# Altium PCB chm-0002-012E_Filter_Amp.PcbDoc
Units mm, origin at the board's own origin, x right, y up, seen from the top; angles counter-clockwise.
Board outline 116 x 29 mm, 4 copper layers (Top Layer, Mid-Layer 1, Mid-Layer 2, Bottom Layer); 56 components, 26 nets, 166 pads, 1068 vias.
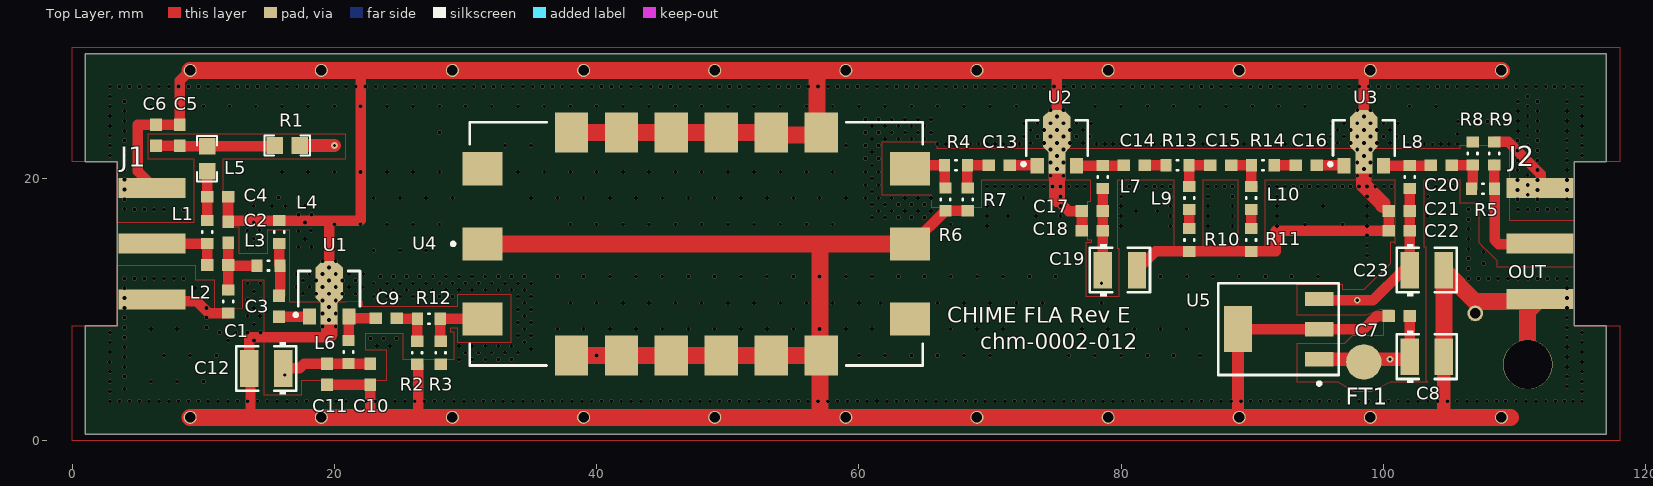
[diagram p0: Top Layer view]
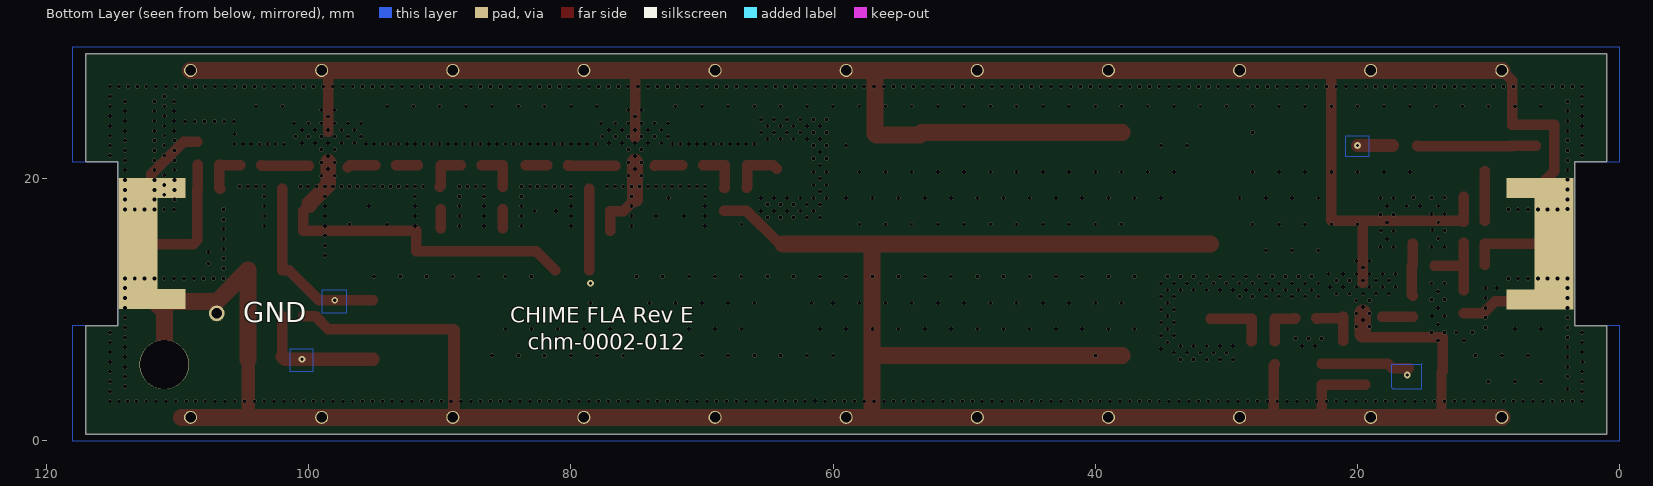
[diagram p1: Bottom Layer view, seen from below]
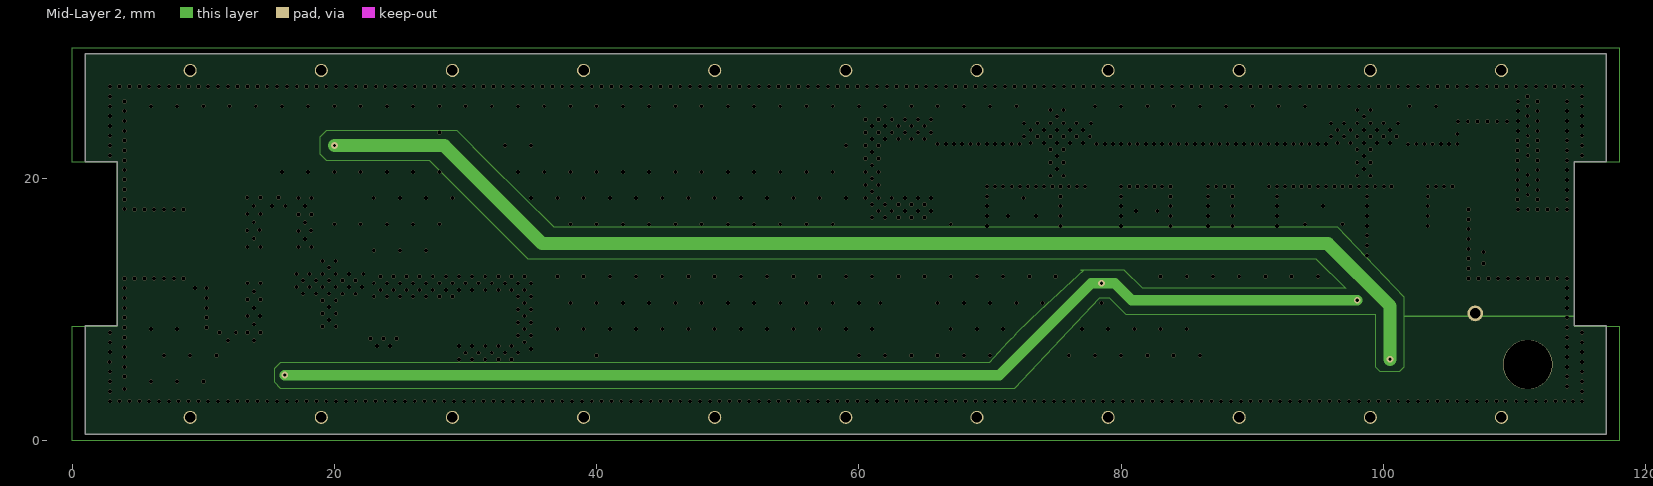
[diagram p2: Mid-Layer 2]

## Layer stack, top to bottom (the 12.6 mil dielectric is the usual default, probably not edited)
Top Solder: solder mask 0.0102, Solder Resist, Dk 3.5
Top Layer: signal copper 0.0356
Dielectric1: core 0.32, FR-4, Dk 4.8
Mid-Layer 1: signal copper 0.0356
Dielectric2: prepreg 0.32, FR-4, Dk 4.8
Mid-Layer 2: signal copper 0.0356
Dielectric3: core 0.32, FR-4, Dk 4.8
Bottom Layer: signal copper 0.0356
Bottom Solder: solder mask 0.0102, Solder Resist, Dk 3.5

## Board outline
1,0.5 1,8.75 3.45,8.75 3.45,21.25 1,21.25 1,29.5 117,29.5 117,21.25 114.55,21.25 114.55,8.75 117,8.75 117,0.5

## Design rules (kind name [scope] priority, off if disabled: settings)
AssemblyTestPointUsage [All] p0: scope1count=1 scope1_0_kind=Board scope1_0_value=Board scope2count=1 scope2_0_kind=Board scope2_0_value=Board commentlength=0
AssemblyTestpoint [All] p0: scope1count=1 scope1_0_kind=Board scope1_0_value=Board scope2count=1 scope2_0_kind=Board scope2_0_value=Board commentlength=0
Clearance [All] p0: scope1count=1 scope1_0_kind=Board scope1_0_value=Board scope2count=1 scope2_0_kind=Board scope2_0_value=Board commentlength=0 gap=0.2
Clearance [All] p1: gap=0.2
ComponentClearance [All] p0: scope1count=1 scope1_0_kind=Board scope1_0_value=Board scope2count=1 scope2_0_kind=Board scope2_0_value=Board commentlength=0 gap=0.254 collisioncheckmode=3
DiffPairsRouting [All] p0: scope1count=1 scope1_0_kind=Board scope1_0_value=Board scope2count=1 scope2_0_kind=Board scope2_0_value=Board commentlength=0
FabricationTestPointUsage [All] p0: scope1count=1 scope1_0_kind=Board scope1_0_value=Board scope2count=1 scope2_0_kind=Board scope2_0_value=Board commentlength=0 valid=0 allowmultiple=FALSE
FabricationTestpoint [All] p0: scope1count=1 scope1_0_kind=Board scope1_0_value=Board scope2count=1 scope2_0_kind=Board scope2_0_value=Board commentlength=0 side=3 testpointundercomponent=TRUE minsize=1.016 maxsize=2.54 preferedsize=1.524 minholesize=0 maxholesize=1.016 preferedholesize=0.813 testpointgrid=0.025
FanoutControl Fanout_Default [All] p0: scope1count=1 scope1_0_kind=Board scope1_0_value=Board scope2count=1 scope2_0_kind=Board scope2_0_value=Board commentlength=30 // Fanout_Default (Default Rule)
FanoutControl Fanout_Small [All] p0 off: scope1count=1 scope1_0_kind=Board scope1_0_value=Board scope2count=1 scope2_0_kind=Board scope2_0_value=Board commentlength=84 // Protel DXP Scope 1 Expression Was: (CompPinCount < 5)   Fanout_Small (Default Rule)
FanoutControl Fanout_SOIC [All] p0 off: scope1count=1 scope1_0_kind=Board scope1_0_value=Board scope2count=1 scope2_0_kind=Board scope2_0_value=Board commentlength=71 // Protel DXP Scope 1 Expression Was: IsSOIC   Fanout_SOIC (Default Rule)
FanoutControl Fanout_LCC [All] p0 off: scope1count=1 scope1_0_kind=Board scope1_0_value=Board scope2count=1 scope2_0_kind=Board scope2_0_value=Board commentlength=69 // Protel DXP Scope 1 Expression Was: IsLCC   Fanout_LCC (Default Rule)
FanoutControl Fanout_BGA [All] p0 off: scope1count=1 scope1_0_kind=Board scope1_0_value=Board scope2count=1 scope2_0_kind=Board scope2_0_value=Board commentlength=69 // Protel DXP Scope 1 Expression Was: IsBGA   Fanout_BGA (Default Rule)
Height [All] p0: scope1count=1 scope1_0_kind=Board scope1_0_value=Board scope2count=1 scope2_0_kind=Board scope2_0_value=Board commentlength=0
HoleSize [All] p0: scope1count=1 scope1_0_kind=Board scope1_0_value=Board scope2count=1 scope2_0_kind=Board scope2_0_value=Board commentlength=0 absolutevalues=TRUE maxlimit=5.5 minlimit=0.025 maxpercent=80.000 minpercent=20.000
HoleSize [All] p1: absolutevalues=TRUE maxlimit=5.5 minlimit=0.025 maxpercent=80.000 minpercent=20.000
HoleToHoleClearance [All] p0: scope1count=1 scope1_0_kind=Board scope1_0_value=Board scope2count=1 scope2_0_kind=Board scope2_0_value=Board commentlength=0
HoleToHoleClearance [All] p1: gap=0.25 allowstackedmicrovias=TRUE
LayerPairs [All] p0: scope1count=1 scope1_0_kind=Board scope1_0_value=Board scope2count=1 scope2_0_kind=Board scope2_0_value=Board commentlength=0 enforce=TRUE
MinimumSolderMaskSliver [All] p0: scope1count=1 scope1_0_kind=Board scope1_0_value=Board scope2count=1 scope2_0_kind=Board scope2_0_value=Board commentlength=0
MinimumSolderMaskSliver [All] p1: minsoldermaskwidth=0.1
NetAntennae [All] p0: scope1count=1 scope1_0_kind=Board scope1_0_value=Board scope2count=1 scope2_0_kind=Board scope2_0_value=Board commentlength=0
PasteMaskExpansion [All] p0: scope1count=1 scope1_0_kind=Board scope1_0_value=Board scope2count=1 scope2_0_kind=Board scope2_0_value=Board commentlength=0 expansion=0
PlaneClearance [All] p0: scope1count=1 scope1_0_kind=Board scope1_0_value=Board scope2count=1 scope2_0_kind=Board scope2_0_value=Board commentlength=0 clearance=0.508
PlaneConnect [All] p0: scope1count=1 scope1_0_kind=Board scope1_0_value=Board scope2count=1 scope2_0_kind=Board scope2_0_value=Board commentlength=0 planeconnectstyle=Direct reliefexpansion=0 reliefentries=4 reliefconductorwidth=0 reliefairgap=0
PlaneConnect [All] p1: planeconnectstyle=Direct reliefexpansion=0 reliefentries=4 reliefconductorwidth=0 reliefairgap=0
PolygonConnect [All] p0: scope1count=1 scope1_0_kind=Board scope1_0_value=Board scope2count=1 scope2_0_kind=Board scope2_0_value=Board commentlength=0 connectstyle=Direct reliefconductorwidth=0 reliefentries=4 polygonreliefangle="90 Angle"
PolygonConnect [All] p1: connectstyle=Direct reliefconductorwidth=0 reliefentries=4 polygonreliefangle="90 Angle" airgapwidth=0
RoutingCorners [All] p0: scope1count=1 scope1_0_kind=Board scope1_0_value=Board scope2count=1 scope2_0_kind=Board scope2_0_value=Board commentlength=0 cornerstyle=45-Degree minsetback=2.54 maxsetback=2.54
RoutingLayers [All] p0: scope1count=1 scope1_0_kind=Board scope1_0_value=Board scope2count=1 scope2_0_kind=Board scope2_0_value=Board commentlength=0 top layer=Automatic mid layer 1=Automatic mid layer 2=Automatic bottom layer=Automatic
RoutingPriority [All] p0: scope1count=1 scope1_0_kind=Board scope1_0_value=Board scope2count=1 scope2_0_kind=Board scope2_0_value=Board commentlength=0
RoutingTopology [All] p0: scope1count=1 scope1_0_kind=Board scope1_0_value=Board scope2count=1 scope2_0_kind=Board scope2_0_value=Board commentlength=0 topology=Shortest
RoutingVias [All] p0: scope1count=1 scope1_0_kind=Board scope1_0_value=Board scope2count=1 scope2_0_kind=Board scope2_0_value=Board commentlength=0 holewidth=0.711 width=1.27 viastyle="Through Hole" minholewidth=0.711 minwidth=1.27 maxholewidth=0.711 maxwidth=1.27
RoutingVias [All] p1: holewidth=0.711 width=1.27 viastyle="Through Hole" minholewidth=0.711 minwidth=1.27 maxholewidth=0.711 maxwidth=1.27
ShortCircuit [All] p0: scope1count=1 scope1_0_kind=Board scope1_0_value=Board scope2count=1 scope2_0_kind=Board scope2_0_value=Board commentlength=0 allowed=FALSE
SilkToBoardRegionClearance [All] p0: scope1count=1 scope1_0_kind=Board scope1_0_value=Board scope2count=1 scope2_0_kind=Board scope2_0_value=Board commentlength=0
SilkToSilkClearance [All] p0: scope1count=1 scope1_0_kind=Board scope1_0_value=Board scope2count=1 scope2_0_kind=Board scope2_0_value=Board commentlength=0
SilkToSilkClearance [All] p1: silktosilkclearance=0.1
SilkToSolderMaskClearance SilkscreenOverComponentPads [All] p0 off: scope1count=1 scope1_0_kind=Board scope1_0_value=Board scope2count=1 scope2_0_kind=Board scope2_0_value=Board commentlength=44 // Protel DXP Scope 1 Expression Was: IsPad
SilkToSolderMaskClearance SilkscreenOverComponentPads [IsPad] p1: minsilkscreentomaskgap=0 clearancetoexposedcopper=TRUE
SolderMaskExpansion [All] p0: scope1count=1 scope1_0_kind=Board scope1_0_value=Board scope2count=1 scope2_0_kind=Board scope2_0_value=Board commentlength=0 expansion=0.1
SolderMaskExpansion [All] p1: expansion=0.1
UnRoutedNet [All] p0: scope1count=1 scope1_0_kind=Board scope1_0_value=Board scope2count=1 scope2_0_kind=Board scope2_0_value=Board commentlength=0
UnpouredPolygon [All] p0: scope1count=1 scope1_0_kind=Board scope1_0_value=Board scope2count=1 scope2_0_kind=Board scope2_0_value=Board commentlength=0
Width [All] p0: scope1count=1 scope1_0_kind=Board scope1_0_value=Board scope2count=1 scope2_0_kind=Board scope2_0_value=Board commentlength=0 maxlimit=1.3 minlimit=0.8 preferedwidth=0.8
Width [All] p1: maxlimit=1.3 minlimit=0.8 preferedwidth=0.8
24 further rules are at their usual default settings.

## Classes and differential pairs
component class "Filter Amplifier Rev D": C1 C2 C3 C4 C5 C6 C7 C8 C9 C10 C11 C12 C13 C14 C15 C16 C17 C18 C19 C20 C21 C22 C23 L1 L2 L3 L4 L5 L6 L7 L8 L9 L10 R1 R2 R3 R4 R5 R6 R7 R8 R9 R10 R11 R12 R13 R14 U1 U2 U3 U4 U5

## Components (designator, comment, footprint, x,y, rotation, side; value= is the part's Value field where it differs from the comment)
C1 "C0603_12p" C1608-0603 11.1,13.4 r0 top
C2 "C0603_2p7" C1608-0603 11.9,15.9 r270 top
C3 "C0603_100p" C1608-0603 15.775,10.25 r270 top
C4 "C0603_100p" C1608-0603 11.1,18.6 r180 top
C5 "C0603_100p" C1608-0603 8.2,23.3 r270 top
C6 "C0603_u1" C1608-0603 6.4,23.3 r270 top
C7 "C0603_u1" C1608-0603 101.2,9.5 r0 top
C8 "Cap Tantalum CC3528" CC3528 103.3,6.4 r0 top
C9 "C0603_100p" C1608-0603 23.95,9.325 r0 top
C10 "C0603_100p" C1608-0603 22.725,5.05 r90 top
C11 "C0603_u1" C1608-0603 19.425,5.075 r90 top
C12 "Cap Tantalum CC3528" CC3528 14.8,5.5 r180 top
C13 "C0603_100p" C1608-0603 70.7,21 r0 top
C14 "C0603_100p" C1608-0603 81,21 r0 top
C15 "C0603_3p9" C1608-0603 87.6,21 r0 top
C16 "C0603_100p" C1608-0603 94.1,21 r180 top
C17 "C0603_100p" C1608-0603 77.8,17.5 r0 top
C18 "C0603_u1" C1608-0603 77.8,16 r180 top
C19 "Cap Tantalum CC3528" CC3528 103.3,13 r0 top
C20 "C0603_100p" C1608-0603 104.4,21 r0 top
C21 "C0603_100p" C1608-0603 101.2,17.5 r0 top
C22 "C0603_u1" C1608-0603 101.2,16 r0 top
C23 "Cap Tantalum CC3528" CC3528 79.9,13 r0 top
J1 "Comment" SMA_EdgeConnector 6.075,10.775 r90 top locked
J2 "Comment" SMA_EdgeConnector 111.95,19.275 r270 top
L1 "Ind0603_51nH" R0603 10.3,15.9 r270 top
L2 "Ind0603_36nH" R0603 11.9,10.6 r90 top
L3 "Ind0603_4n7H" R0603 14.975,13.35 r0 top
L4 "Ind0603_72nH" R0603 15.8,15.9 r270 top
L5 "Ind0805_100nH" "0805 LRC" 10.3,21.5 r90 top
L6 "Ind0603_100nH" R0603 21.075,6.75 r90 top
L7 "Ind0603_100nH" R0603 78.6,20.1 r90 top
L8 "Ind0603_100nH" R0603 102,20.1 r90 top
L9 "Ind0603_15nH" R0603 85.2,18.5 r90 top
L10 "Ind0603_15nH" R0603 89.9,18.5 r90 top
R1 "R0805_0R" "0805 LRC" 16.4,22.5 r0 top
R2 "R603_270R1" R0603 26.3,6.7 r90 top
R3 "R603_270R1" R0603 28.1,6.7 r90 top
R4 "R603_6R2" R0603 67.4,21 r0 top
R5 "R603_6R2" R0603 107.6,19.2 r0 top
R6 "R603_82R1" R0603 66.6,18.4 r90 top
R7 "R603_82R1" R0603 68.3,18.4 r90 top
R8 "R603_82R1" R0603 106.8,21.9 r270 top
R9 "R603_82R1" R0603 108.45,21.9 r270 top
R10 "R603_47R0" R0603 85.2,15.3 r90 top
R11 "R603_47R0" R0603 89.9,15.3 r270 top
R12 "R603_18R0" R0603 27.2,9.3 r0 top
R13 "R603_2R7" R0603 84.3,21 r0 top
R14 "R603_2R7" R0603 90.8,21 r0 top
U1 "MGA-30889" SOT-89 19.6,11.6 r90 top
U2 "MGA-30889" SOT-89 75.1,23.1 r90 top
U3 "MGA-30889" SOT-89 98.5,23.1 r90 top
U4 "BPF-600-2+" MiniCcts_HP1156 47.6,15 r90 top
U5 "LT1129IST-5" SOT-223 92,8.5 r90 top
? "" "UBC Logo" 90.975,9.575 r180 bottom
? "" "UBC Logo" 24.075,22.625 r0 top

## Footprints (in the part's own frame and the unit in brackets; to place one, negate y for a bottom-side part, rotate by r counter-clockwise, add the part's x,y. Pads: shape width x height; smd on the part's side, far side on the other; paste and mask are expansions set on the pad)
"0805 LRC" [mm] "Generic 0805 reduced footprint"
  rect 1.27x1.27 smd: 1(-0.95,0) 2(0.95,0)
  silkscreen extent -1.73,-0.76 1.73,0.76
C1608-0603 [mm] "Chip Capacitor, 2-Leads, Body 1.60x0.80mm, IPC Medium Density"
  rect 0.95x0.9 smd: 1(-0.8,0) 2(0.8,0)
CC3528 [mm]
  rect 1.4x2.8 smd: 1(-1.3,0) 2(1.3,0)
  silkscreen extent -2.3,-2 2.3,2
MiniCcts_HP1156 [mm] "Mini Circuits Filter BPF-600-2+"
  rect 2.54x3.05 smd: 1(0,16.3) 2(-5.72,16.3) 9(-5.72,-16.3) 10(0,-16.3) 11(5.72,-16.3) 18(5.72,16.3)
  rect 3.05x2.54 smd: 3(-8.51,9.525) 4(-8.51,5.715) 5(-8.51,1.905) 6(-8.51,-1.905) 7(-8.51,-5.715) 8(-8.51,-9.525) 12(8.51,-9.525) 13(8.51,-5.715) 14(8.51,-1.905) 15(8.51,1.905) 16(8.51,5.715) 17(8.51,9.525)
  silkscreen extent -9.27,-17.27 9.27,18.67
R0603 [mm] "Chip Resistor, 2-Leads, Body 1.60x0.80mm, IPC Medium Density"
  rect 0.85x0.95 smd: 1(-0.875,0) 2(0.875,0)
  silkscreen extent -0.05,-0.38 0.05,0.38
SMA_EdgeConnector [mm]
  rect 1.53x5.1 smd: 1(4.24,0) 2(0,0) 2(8.48,0)
  rect 1.53x5.1 smd far side: 2(0,0) 2(8.48,0)
  rect 9.5x3 smd far side: 2(4.24,1.05)
SOT-89 [mm] "SOT89, 3-Leads, Body 4.5x2.6mm (max), Pitch 1.50mm, Lead Span 3.6mm, IPC Medium Density"
  rect 1.2x1 smd: 1(-2.138,1.5) 3(-2.138,-1.5)
  rect 1.8x1.3 smd: 2(-1.837,0)
  oct 3.35x2.1 smd: 4(0.438,0)
  silkscreen extent -2.14,-2.35 1.34,2.67
SOT-223 [mm]
  rect 1.1x2.15 smd: 1(-2.3,-3.1) 2(0,-3.1) 3(2.3,-3.1)
  rect 3.5x2.15 smd: 4(0,3.1)
  silkscreen extent -4.27,-4.6 3.5,4.6
"UBC Logo" [mm] "UBC Silkscreen Logo - 288mil x 392mil"

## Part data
C1: "12pf 1% 0603 50V NPO"
C2: "2.7pf  +- .1pf 50V NPO(COG)"
C3 C4 C5 C9 C10 C13 C14 C16 C17 C20 C21: "100pf Ceramic NPO 0603 Capacitor"
C6 C7 C11 C18 C22: "u1 Ceramic X7R 0603 Capacitor"
C8 C12 C19 C23: "SM Tantalum Capacitor 10u 25V B-size Low ESR"
C15: "3.9pf  +-.1pf 0603 50V NPO"
L1: "51nH 2% 0603 370mA"
L2: "36nH 2% 0603"
L3: "4.7nH 2% RF Inductor"
L4: "72nH 2% 0603"
L5: "100nH 0805 Inductor"
L6 L7 L8: "100nH 0603 5% 220mA"
L9 L10: "15nH 2% 0603"
R1: "0R 0805 1% Resistor"
R2 R3: "271R 0603 0.5% Thin Film 1/16W 100ppm Resistor"
R4 R5: "6R2 0603 1/16W 1% 200ppm Thin Film Resistor"
R6 R7 R8 R9: "82R1 0.5% 25ppm 0603 Thin Film Resistor"
R10 R11: "47R 1% 200ppm 1/5W 0603 Thin Film Resistor"
R12: "18R 0603 1/16W 0.5% Thin Film Resistor"
R13 R14: "2R7 0603 1% 200ppm Thin Film Resistor"
U1 U2 U3: "40MHz-2600MHz Flat Gain High Linearity Gain Block MGA-30889"
U4: "Band Pass Filter"
U5: "LDO +5V Regulator 700mA"

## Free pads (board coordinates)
  round 1 hole 0.8: 0(9,1.77) 0(9,28.23) 0(19,1.77) 0(19,28.23) 0(29,1.77) 0(29,28.23) 0(39,1.77) 0(39,28.23) 0(49,1.77) 0(49,28.23) 0(59,1.77) 0(59,28.23) 0(69,1.77) 0(69,28.23) 0(79,1.77) 0(79,28.23) 0(89,1.77) 0(89,28.23) 0(99,1.77) 0(99,28.23) 0(109,1.77) 0(109,28.23)
  round 2.7 smd: 0(98.5,6)
  round 2.7 on Top Solder: 0(98.5,6)
  round 1.2 hole 0.8: 0(107,9.7)
  round 4 on Bottom Solder: 2(103.65,6.45)

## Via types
v1: diameter 0.3, hole 0.3, Top Layer to Bottom Layer, 1062 vias
v2: diameter 0.508, hole 0.254, Top Layer to Bottom Layer, 5 vias
v3: diameter 3.75, hole 3.73, Top Layer to Bottom Layer, 1 vias

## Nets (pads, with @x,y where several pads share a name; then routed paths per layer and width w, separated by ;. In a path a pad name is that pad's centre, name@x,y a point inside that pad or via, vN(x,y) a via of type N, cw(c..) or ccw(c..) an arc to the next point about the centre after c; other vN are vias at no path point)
GND: C2.1 C4.1 C5.1 C6.1 C7.1 C8.2 C10.1 C11.1 C12.2 C17.1 C18.2 C19.2 C21.1 C22.1 C23.2 J1.2 J2.2 L2.1 L4.1 pad.0@9,1.77 pad.0@9,28.23 pad.0@19,1.77 pad.0@19,28.23 pad.0@29,1.77 pad.0@29,28.23 pad.0@39,1.77 pad.0@39,28.23 pad.0@49,1.77 pad.0@49,28.23 pad.0@59,1.77 pad.0@59,28.23 pad.0@69,1.77 pad.0@69,28.23 pad.0@79,1.77 pad.0@79,28.23 pad.0@89,1.77 pad.0@89,28.23 pad.0@99,1.77 pad.0@99,28.23 pad.0@107,9.7 pad.0@109,1.77 pad.0@109,28.23 R2.1 R3.1 R6.1 R7.1 R8.1 R9.1 R10.1 R11.2 U1.2 U1.4 U2.2 U2.4 U3.2 U3.4 U4.1 U4.3 U4.4 U4.5 U4.6 U4.7 U4.8 U4.10 U4.12 U4.13 U4.14 U4.15 U4.16 U4.17 U5.2 U5.4 | length 459.4
  Top Layer w0.8: J1.2@6.057,10.625 9.5,10.625 10.4,9.725 L2.1 ; J1.2@6.15,19.382 5,20.532 5,24.1 C6.1 C5.1 8.2,27.43 pad.0@9,28.23 ; C2.1 C4.1 ; C2.1@11.975,16.775 L4.1 19.5,16.775 ; 13.6,1.77 13.6,5.2 13.5,5.3 13.5,7.85 13.525,7.875 19.35,7.875 19.6,8.125 ; C11.1 19.45,4.25 C10.1 22.725,1.905 22.86,1.77 ; U1.4 19.6,16.675 19.5,16.775 ; 21.9,28.23 22,28.13 22,16.8 21.975,16.775 19.5,16.775 ; R2.1 26.4,5.725 26.4,1.77 ; U4.10@63.8,15 64.075,15 R6.1 R7.1 ; 75.1,18.4 76,17.5 C17.1 C18.2 ; U2.4@75.1,23.1 75.1,28.23 ; C23.2 82.625,14.425 R11.2 91.8,14.425 91.8,16 C22.1 C21.1 C21.1@99.95,17.95 ; U5.4@88.9,8.4 89,8.5 U5.2 98.5,8.5 99.5,9.5 C7.1 ; U3.4 98.5,27.73 pad.0@99,28.23 ; 108.3,28.23 108.5,28.03 ; R9.1@108.5,22.775 109.475,22.775 109.5,22.8 112,20.3 J2.2@112,19.382
  Top Layer w0.9: U5.4@88.9,8.4 88.9,1.87 pad.0@89,1.77
  Top Layer w1: 104.5,1.77 104.6,1.87 C8.2@104.6,6.2
  Top Layer w1.2: 75.1,18.4 U2.2 ; U3.2 98.5,19.5 99.95,18.05 C21.1@99.95,17.95
  Top Layer w1.25: 19.6,8.125 U1.2
  Top Layer w1.3: pad.0@9,1.77 13.6,1.77 19,1.77 22.86,1.77 26.4,1.77 29,1.77 39,1.77 49,1.77 56.9,1.77 ; pad.0@9,28.23 19,28.23 21.9,28.23 29,28.23 39,28.23 49,28.23 56.8,28.23 ; U4.1@31.2,15 56.9,15 ; U4.3@37.975,6.49 U4.8@57.025,6.49 ; U4.17@37.975,23.51 53.215,23.51 53.425,23.3 56.7,23.3 56.8,23.4 56.8,28.23 ; 57.025,28.005 56.8,28.23 ; U4.10@63.8,15 56.9,15 ; C8.2@104.6,6.2 C19.2 106.982,10.619 111.721,10.619 111,9.898 v3(111,5.8) ; pad.0@109,28.23 108.3,28.23 99,28.23 89,28.23 79,28.23 75.1,28.23 69,28.23 59,28.23 56.8,28.23 ; 109.67,1.77 109,1.77 104.5,1.77 99,1.77 90.9,1.77 89,1.77 79,1.77 69,1.77 59,1.77 56.9,1.77 ; 56.9,1.77 57.025,1.895 U4.8@57.025,6.49 ; 56.9,15 57.025,14.875 U4.8@57.025,6.49
  other v1: 2.875,3 3.625,3 4.375,3 5.125,3 5.875,3 6.625,3 7.375,3 8.125,3 8.875,3 9.625,3 10.375,3 11.125,3 11.875,3 12.625,3 13.375,3 14.125,3 14.875,3 15.625,3 16.375,3 17.125,3 17.875,3 18.625,3 19.375,3 20.125,3 20.875,3 21.625,3 22.375,3 23.125,3 23.875,3 24.625,3 25.375,3 26.125,3 26.875,3 27.625,3 28.375,3 29.125,3 29.875,3 30.625,3 31.375,3 32.125,3 32.85,3 33.625,3 34.375,3 35.125,3 35.875,3 36.625,3 37.375,3 38.125,3 38.875,3 39.625,3 40.375,3 41.125,3 41.875,3 42.625,3 43.375,3 44.125,3 44.875,3 45.625,3 46.375,3 47.125,3 47.875,3 48.625,3 49.375,3 50.125,3 50.875,3 51.625,3 52.375,3 53.125,3 53.875,3 54.625,3 55.375,3 56.125,3 56.875,3 57.625,3 58.375,3 59.125,3 59.875,3 60.625,3 62.125,3 62.875,3 63.625,3 64.375,3 65.125,3 65.875,3 66.625,3 67.375,3 68.125,3 68.875,3 69.625,3 70.375,3 71.125,3 71.875,3 72.625,3 73.375,3 74.125,3 74.875,3 75.625,3 76.375,3 77.125,3 77.875,3 78.625,3 79.375,3 80.125,3 80.875,3 81.625,3 82.375,3 83.125,3 83.875,3 84.625,3 85.375,3 86.125,3 86.875,3 87.625,3 88.375,3 89.125,3 89.875,3 90.625,3 91.375,3 92.125,3 92.875,3 93.625,3 94.375,3 95.125,3 95.875,3 96.625,3 97.375,3 98.125,3 98.875,3 99.625,3 100.375,3 101.125,3 101.875,3 102.625,3 103.375,3 104.125,3 104.875,3 105.625,3 106.375,3 107.125,3 107.875,3 108.625,3 109.3,3 110.125,3 110.875,3 111.625,3 112.375,3 113.125,3 113.8,3 114.45,3 115.125,3 61.375,3.025 2.875,3.75 115.125,3.75 3.975,3.95 114,4.125 2.875,4.5 6,4.5 8,4.5 10,4.5 115.125,4.5 4,4.875 114,4.875 2.875,5.25 115.125,5.25 4,5.625 114,5.625 2.85,6 115.125,6 29.5,6.2 30.5,6.2 31.5,6.2 32.5,6.2 33.5,6.2 4,6.375 114,6.375 7,6.5 9,6.5 11,6.5 40,6.5 60,6.5 62,6.5 64,6.5 66,6.5 68,6.5 70,6.5 76,6.5 78,6.5 80,6.5 82,6.5 84,6.5 86,6.5 30,6.7 31,6.7 32,6.7 33,6.7 34,6.7 2.875,6.75 115.125,6.75 35,7 4,7.125 114,7.125 23.25,7.2 24.25,7.2 29.5,7.2 30.5,7.2 31.5,7.2 32.5,7.2 33.5,7.2 2.875,7.5 34.5,7.5 115.125,7.5 11.875,7.65 13.875,7.65 22.75,7.8 23.75,7.8 24.75,7.8 4,7.875 114,7.875 34,8 35,8 2.875,8.25 11.25,8.25 12.475,8.25 13.375,8.25 14.375,8.25 115.125,8.25 6,8.5 8,8.5 34.5,8.5 37,8.5 39,8.5 41,8.5 43,8.5 45,8.5 47,8.5 49,8.5 51,8.5 53,8.5 55,8.5 57,8.5 59,8.5 61,8.5 67,8.5 69,8.5 71,8.5 77,8.5 79,8.5 81,8.5 83,8.5 85,8.5 4,8.625 10.25,8.625 114,8.625 19.1,8.7 20.1,8.7 13.875,8.875 34,9 35,9 19.6,9.2 4,9.375 10.25,9.375 114,9.375 13.375,9.5 14.325,9.5 34.5,9.5 19.1,9.7 20.1,9.7 34,10 35,10 4,10.125 10.25,10.125 13.875,10.125 114,10.125 19.6,10.2 34.5,10.5 38,10.5 40,10.5 42,10.5 44,10.5 46,10.5 48,10.5 50,10.5 52,10.5 54,10.5 56,10.5 58,10.5 60,10.5 61.625,10.5 66,10.5 68,10.5 70,10.5 72,10.5 74,10.5 78.5,10.5 19.1,10.7 20.1,10.7 13.375,10.75 14.375,10.75 4,10.875 10.25,10.875 114,10.875 23,11 24,11 25,11 26,11 27,11 28,11 29,11 34,11 35,11 17.6,11.2 18.6,11.2 19.6,11.2 20.6,11.2 21.6,11.2 13.875,11.375 23.5,11.5 24.5,11.5 25.5,11.5 26.5,11.5 27.5,11.5 28.5,11.5 29.5,11.5 30.5,11.5 31.5,11.5 32.5,11.5 33.5,11.5 34.5,11.5 4,11.625 9.375,11.625 10.25,11.625 114,11.625 17.1,11.7 18.1,11.7 19.1,11.7 20.1,11.7 21.1,11.7 22.1,11.7 13.375,12 14.375,12 23,12 24,12 25,12 26,12 27,12 28,12 29,12 30,12 31,12 32,12 33,12 34,12 35,12 17.6,12.2 18.6,12.2 19.6,12.2 20.6,12.2 21.6,12.2 4,12.375 4.75,12.375 5.5,12.375 6.25,12.375 7,12.375 7.75,12.375 8.5,12.375 106.5,12.375 107.25,12.375 108,12.375 108.75,12.375 109.5,12.375 110.25,12.375 111,12.375 111.75,12.375 112.5,12.375 113.25,12.375 114,12.375 23.5,12.5 24.5,12.5 25.5,12.5 26.5,12.5 27.5,12.5 28.5,12.5 29.5,12.5 30.5,12.5 31.5,12.5 32.5,12.5 33.5,12.5 34.5,12.5 37,12.5 39,12.5 41,12.5 43,12.5 45,12.5 47,12.5 49,12.5 51,12.5 53,12.5 55,12.5 57,12.5 59,12.5 61,12.5 63,12.5 65,12.5 67,12.5 69,12.5 71,12.5 73,12.5 75,12.5 83,12.5 85,12.5 87,12.5 89,12.5 91,12.5 93,12.5 95,12.5 17.1,12.7 18.1,12.7 19.1,12.7 20.1,12.7 21.1,12.7 22.2,12.7 106.5,13.125 19.6,13.2 107.625,13.5 19.1,13.7 20.1,13.7 106.5,13.875 98.75,14.125 107.625,14.375 23,14.5 25,14.5 27,14.5 106.5,14.625 17.25,14.75 18.25,14.75 13.35,14.775 14.35,14.775 98.75,14.875 17.75,15.375 106.5,15.375 13.85,15.4 98.75,15.625 17.25,16 13.35,16.025 18.2,16.025 14.3,16.05 106.5,16.125 69.75,16.375 75.375,16.375 80,16.375 83.75,16.375 86.625,16.375 88.5,16.375 91.875,16.375 98.75,16.375 103.375,16.375 20,16.5 22,16.5 24,16.5 26,16.5 28,16.5 38,16.5 40,16.5 42,16.5 44,16.5 46,16.5 48,16.5 50,16.5 52,16.5 54,16.5 56,16.5 58,16.5 67,16.5 94,16.5 96.875,16.5 17.75,16.625 13.85,16.65 106.5,16.875 61,17 62,17 63,17 64,17 65,17 69.75,17.125 71.375,17.125 73.5,17.125 75.375,17.125 80,17.125 83.75,17.125 86.625,17.125 88.5,17.125 91.875,17.125 98.75,17.125 103.375,17.125 17.25,17.25 18.25,17.25 13.35,17.275 14.35,17.275 61.5,17.5 62.5,17.5 63.5,17.5 64.5,17.5 65.5,17.5 81.125,17.5 82.75,17.525 4.75,17.625 5.5,17.625 6.25,17.625 7,17.625 7.75,17.625 8.5,17.625 106.5,17.625 110.25,17.625 111,17.625 111.75,17.625 112.5,17.625 113.25,17.625 114,17.625 4,17.65 17.75,17.875 69.75,17.875 75.375,17.875 80,17.875 83.75,17.875 86.625,17.875 88.5,17.875 91.875,17.875 95.375,17.875 98.75,17.875 103.375,17.875 13.85,17.9 15.25,17.9 16.25,17.9 61,18 62,18 63,18 64,18 65,18 110.225,18.375 111.75,18.375 114,18.375 4,18.4 17.25,18.5 18.25,18.5 23,18.5 25,18.5 27,18.5 29,18.5 35,18.5 37,18.5 39,18.5 41,18.5 43,18.5 45,18.5 47,18.5 49,18.5 51,18.5 53,18.5 55,18.5 57,18.5 59,18.5 60.5,18.5 61.5,18.5 62.5,18.5 63.5,18.5 64.5,18.5 65.5,18.5 72.55,18.5 13.35,18.525 14.35,18.525 15.75,18.525 69.75,18.625 75.375,18.625 80,18.625 83.75,18.625 86.625,18.625 88.5,18.625 91.875,18.625 98.75,18.625 103.375,18.625 111,18.75 61,19 110.225,19.125 111.75,19.125 114,19.125 4,19.15 69.75,19.375 70.375,19.375 71,19.375 71.65,19.375 72.275,19.375 72.875,19.375 73.5,19.375 74.1,19.375 74.75,19.375 75.375,19.375 76,19.375 76.625,19.375 77.25,19.375 80,19.375 80.625,19.375 81.25,19.375 81.875,19.375 82.525,19.375 83.125,19.375 83.75,19.375 86.625,19.375 87.25,19.375 87.875,19.375 88.5,19.375 91.25,19.375 91.875,19.375 92.5,19.375 93.125,19.375 93.75,19.375 94.375,19.375 95,19.375 95.625,19.375 96.25,19.375 96.875,19.375 97.5,19.375 98.125,19.375 98.75,19.375 99.375,19.375 100.025,19.375 100.625,19.375 103.375,19.375 104,19.375 104.625,19.375 105.25,19.375 60.5,19.5 61.5,19.5 111,19.5 110.225,19.875 111.75,19.875 114,19.875 4,19.9 61,20 74.6,20.2 75.6,20.2 98,20.2 99,20.2 111,20.25 16,20.5 18,20.5 20,20.5 22,20.5 24,20.5 26,20.5 28,20.5 34,20.5 36,20.5 38,20.5 40,20.5 42,20.5 44,20.5 46,20.5 48,20.5 50,20.5 52,20.5 54,20.5 56,20.5 58,20.5 60.5,20.5 61.5,20.5 4,20.625 110.225,20.625 111.75,20.625 114,20.625 75.1,20.7 98.5,20.7 61,21 74.6,21.2 75.6,21.2 98,21.2 99,21.2 4,21.375 110.225,21.375 111.75,21.375 114,21.375 60.5,21.5 61.5,21.5 75.1,21.7 98.5,21.7 2.875,21.75 111,21.75 115.125,21.75 61,22 4,22.125 110.225,22.125 111.75,22.125 114,22.125 74.6,22.2 75.6,22.2 98,22.2 99,22.2 2.875,22.5 33,22.5 35,22.5 59,22.5 60.5,22.5 61.5,22.5 111,22.5 115.125,22.5 101.875,22.6 103.75,22.6 66,22.625 66.625,22.625 67.25,22.625 67.875,22.625 68.5,22.625 69.125,22.625 69.75,22.625 70.375,22.625 71,22.625 71.625,22.625 72.25,22.625 78.125,22.625 78.75,22.625 79.375,22.625 80,22.625 80.625,22.625 81.25,22.625 81.875,22.625 82.5,22.625 83.125,22.625 83.75,22.625 84.375,22.625 85,22.625 85.625,22.625 86.25,22.625 86.875,22.625 87.5,22.625 88.125,22.625 88.75,22.625 89.375,22.625 90,22.625 90.625,22.625 91.25,22.625 91.875,22.625 92.5,22.625 93.125,22.625 93.75,22.625 94.375,22.625 95,22.625 95.625,22.625 102.5,22.625 103.125,22.625 104.375,22.625 105,22.625 105.625,22.625 73.1,22.7 74.1,22.7 75.1,22.7 76.1,22.7 77.1,22.7 96.5,22.7 97.5,22.7 98.5,22.7 99.5,22.7 100.5,22.7 4,22.875 110.225,22.875 111.75,22.875 114,22.875 61,23 62,23 63,23 64,23 65,23 72.6,23.2 73.6,23.2 74.6,23.2 75.6,23.2 76.6,23.2 77.6,23.2 96,23.2 97,23.2 98,23.2 99,23.2 100,23.2 101,23.2 2.875,23.25 111,23.25 115.125,23.25 105.625,23.375 28,23.5 60.5,23.5 61.5,23.5 62.5,23.5 63.5,23.5 64.5,23.5 65.5,23.5 4,23.625 110.25,23.625 111.75,23.625 114,23.625 73.1,23.7 74.1,23.7 75.1,23.7 76.1,23.7 77.1,23.7 96.5,23.7 97.5,23.7 98.5,23.7 99.5,23.7 100.5,23.7 2.875,24 61,24 62,24 63,24 64,24 65,24 111,24 115.125,24 72.6,24.2 73.6,24.2 74.6,24.2 75.6,24.2 76.6,24.2 77.7,24.2 96,24.2 97,24.2 98,24.2 99,24.2 100,24.2 101.1,24.2 105.675,24.325 106.425,24.325 107.175,24.325 107.925,24.325 108.675,24.325 109.425,24.325 4,24.375 110.25,24.375 111.75,24.375 114,24.375 60.5,24.5 61.5,24.5 62.5,24.5 63.5,24.5 64.5,24.5 65.5,24.5 75.1,24.7 98.5,24.7 2.875,24.75 110.975,24.75 115.125,24.75 4,25.125 110.25,25.125 111.75,25.125 114,25.125 74.6,25.2 75.6,25.2 98,25.2 99,25.2 2.875,25.5 6,25.5 8,25.5 10,25.5 12,25.5 14,25.5 16,25.5 18,25.5 20,25.5 22,25.5 24,25.5 26,25.5 28,25.5 30,25.5 32,25.5 34,25.5 36,25.5 38,25.5 40,25.5 42,25.5 44,25.5 46,25.5 48,25.5 50,25.5 52,25.5 54,25.5 56,25.5 58,25.5 60,25.5 62,25.5 64,25.5 66,25.5 68,25.5 70,25.5 72,25.5 78,25.5 80,25.5 82,25.5 84,25.5 86,25.5 88,25.5 90,25.5 92,25.5 94,25.5 102,25.5 104,25.5 110.975,25.5 115.125,25.5 4,25.875 110.25,25.875 111.75,25.875 114,25.875 2.875,26.25 110.975,26.25 115.125,26.25 2.875,27 3.625,27 4.375,27 5.125,27 5.875,27 6.625,27 7.375,27 8.125,27 8.875,27 9.625,27 10.375,27 11.125,27 11.875,27 12.625,27 13.375,27 14.125,27 14.875,27 15.625,27 16.375,27 17.125,27 17.875,27 18.625,27 19.375,27 20.125,27 20.875,27 21.625,27 22.375,27 23.15,27 23.875,27 24.625,27 25.375,27 26.125,27 26.875,27 27.625,27 28.375,27 29.125,27 29.875,27 30.625,27 31.375,27 32.125,27 32.875,27 33.625,27 34.375,27 35.125,27 35.875,27 36.625,27 37.375,27 38.125,27 38.875,27 39.625,27 40.375,27 41.125,27 41.875,27 42.625,27 43.375,27 44.125,27 44.875,27 45.625,27 46.375,27 47.125,27 47.875,27 48.625,27 49.375,27 50.125,27 50.875,27 51.625,27 52.375,27 53.125,27 53.875,27 54.625,27 55.375,27 56.125,27 56.875,27 57.625,27 58.375,27 59.125,27 59.875,27 60.625,27 61.375,27 62.125,27 62.875,27 63.625,27 64.375,27 65.125,27 65.875,27 66.625,27 67.375,27 68.125,27 68.875,27 69.625,27 70.375,27 71.125,27 71.875,27 72.625,27 73.375,27 74.125,27 74.875,27 75.625,27 76.375,27 77.125,27 77.875,27 78.625,27 79.375,27 80.125,27 80.875,27 81.625,27 82.375,27 83.125,27 83.875,27 84.625,27 85.375,27 86.125,27 86.875,27 87.625,27 88.375,27 89.125,27 89.875,27 90.625,27 91.375,27 92.125,27 92.875,27 93.625,27 94.375,27 95.125,27 95.875,27 96.625,27 97.375,27 98.125,27 98.875,27 99.625,27 100.375,27 101.125,27 101.875,27 102.625,27 103.375,27 104.125,27 104.875,27 105.625,27 106.375,27 107.125,27 107.875,27 108.625,27 109.375,27 110.125,27 110.875,27 111.625,27 112.375,27 113.05,27 113.75,27 114.45,27 115.125,27.025
NetC1_1: C1.1 J1.1 L1.2 | length 6.1
  Top Layer w0.8: J1.1@5.85,15.025 L1.2 C1.1
NetC1_2: C1.2 C2.2 L2.2 L3.1 | length 5.8
  Top Layer w0.8: L2.2 C1.2 ; C2.2 C1.2 ; L3.1 11.95,13.35 C1.2
NetC3_1: C3.1 L3.2 L4.2 | length 4
  Top Layer w0.8: C3.1 15.85,11.125 L3.2 15.8,13.4 L4.2
NetC3_2: C3.2 U1.1 | length 2.3
  Top Layer w0.8: C3.2 18.088,9.45 U1.1
NetC4_2: C4.2 L1.1 L5.1 | length 3.8
  Top Layer w0.8: L1.1 C4.2 L5.1
NetC5_2: C5.2 C6.2 L5.2 R1.1 | length 9.1
  Top Layer w0.8: C6.2 C5.2 8.25,22.45 L5.2 15.4,22.45 R1.1
NetC7_2: C7.2 C8.1 pad.0@98.5,6 R1.2 U5.1 | length 102.4
  Top Layer w0.8: C8.1 C7.2
  Top Layer w1: R1.2 v2(20,22.5) ; U5.1 v2(100.5,6.2) 101.8,6.2 C8.1
  Mid-Layer 2 w1: v2(20,22.5) 28.375,22.5 35.85,15.025 95.75,15.025 100.5,10.275 v2(100.5,6.2)
NetC9_1: C9.1 L6.2 U1.3 | length 4
  Top Layer w0.8: L6.2 21.1,7.65 U1.3 21.238,9.325 C9.1 ; C9.1@23.075,9.275 C9.1@23.1,9.3
NetC9_2: C9.2 R2.2 R12.1 | length 3.3
  Top Layer w0.8: C9.2 24.775,9.3 R12.1 26.325,7.6 R2.2
NetC13_1: C13.1 R4.2 R7.2 | length 3.4
  Top Layer w0.8: R7.2 68.275,19.3 R4.2 C13.1
NetC13_2: C13.2 U2.1 | length 2.1
  Top Layer w0.8: C13.2 73.562,21 U2.1
NetC14_1: C14.1 L7.2 U2.3 | length 3.5
  Top Layer w0.8: U2.3 L7.2@78.487,20.963 ; L7.2 80.175,20.975 C14.1
NetC14_2: C14.2 R13.1 | length 1.6
  Top Layer w0.8: C14.2 R13.1
NetC15_1: C15.1 L9.2 R13.2 | length 3.3
  Top Layer w0.8: L9.2 85.2,20.975 R13.2 C15.1
NetC15_2: C15.2 L10.2 R14.1 | length 3.2
  Top Layer w0.8: C15.2 R14.1 89.925,19.45 L10.2@90,19.375
NetC16_1: C16.1 U3.1 | length 2.2
  Top Layer w0.8: C16.1 96.863,21 U3.1@97,20.863
NetC16_2: C16.2 R14.2 | length 1.6
  Top Layer w0.8: R14.2 C16.2
NetC20_1: C20.1 L8.2 U3.3 | length 3.6
  Top Layer w0.8: U3.3 101.988,20.963 L8.2 103.575,20.975 C20.1
NetC20_2: C20.2 R5.1 R8.2 | length 3.5
  Top Layer w0.8: C20.2 106.775,21 R8.2 106.8,19.275 R5.1
NetJ2_1: J2.1 R5.2 R9.2 | length 9.4
  Top Layer w0.8: R9.2 108.45,19.225 R5.2 108.475,15.3 108.8,14.975 111.925,14.975 J2.1@111.95,15
NetL9_1: L9.1 R10.2 | length 1.4
  Top Layer w0.8: R10.2 L9.1
NetL10_1: L10.1 R11.1 | length 1.4
  Top Layer w0.8: R11.1 L10.1
NetR3_2: R3.2 R12.2 U4.2 | length 4.9
  Top Layer w0.8: R3.2 28.075,7.6 R12.2 31.18,9.3 U4.2@31.2,9.28
NetR4_1: R4.1 R6.2 U4.11 | length 4.1
  Top Layer w0.8: U4.11@64.3,20.72 64.58,21 R4.1 66.525,19.35 R6.2
VDD: C10.2 C11.2 C12.1 C17.2 C18.1 C19.1 C21.2 C22.2 C23.1 L6.1 L7.1 L8.1 U5.3 | length 112.3
  Top Layer w0.8: C12.1 17.325,5.5 17.7,5.875 C11.2 L6.1 21.1,5.85 C10.2 ; C23.1 C18.1 C17.2 L7.1 ; U5.3@95.1,10.7 99.2,10.7 101.5,13 C19.1 102,15.9 102,17.6 L8.1
  Mid-Layer 2 w0.8: v2(16.2,5) 70.7,5 77.7,12 79.5,12 80.8,10.7 v2(98,10.7)
  other v2: 78.5,12
pads on no net: U4.9 U4.18

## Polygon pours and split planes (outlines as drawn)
GND on Mid-Layer 1 "Middle Layer Polygon" (solid, pour order 22): 3.45,8.75 3.45,21.25 0,21.25 0,30 118,30 118,21.25 114.55,21.25 114.55,8.75 118,8.75 118,0 86.125,0 78.6,0 0,0 0,8.75
GND on Bottom Layer "Bottom Layer-No Net" (solid, pour order 34): 19.1,23.225 20.95,23.225 20.95,21.7 19.1,21.7 19.1,23.225
GND on Bottom Layer "Bottom Layer-No Net" (solid, pour order 32): 99.625,6.95 101.45,6.95 101.45,5.275 99.625,5.275 99.625,6.95
GND on Bottom Layer "Bottom Layer-No Net" (solid, pour order 30): 97.075,11.475 98.975,11.475 98.975,9.75 97.075,9.75 97.075,11.475
GND on Bottom Layer "Bottom Layer-No Net" (solid, pour order 26): 15.125,5.85 15.175,5.8 17.425,5.8 17.425,4.05 17.325,3.95 15.1,3.95 15.1,5.825
GND on Bottom Layer "Bottom Layer Polygon" (solid, pour order 20): 0,8.75 3.45,8.75 3.45,21.25 0,21.25 0,30 118,30 118,21.25 114.55,21.25 114.55,8.75 118,8.75 118,0 0,0
GND on Mid-Layer 2 "Mid-Layer 2 Polygon" (solid, pour order 24): -0.002,8.727 3.448,8.727 3.448,21.227 -0.002,21.227 -0.002,29.977 117.998,29.977 117.998,21.227 114.548,21.227 114.548,9.502 101.598,9.502 101.598,10.2 101.598,10.925 96.498,16.252 36.748,16.252 31.823,21.152 29.348,23.627 19.373,23.627 18.873,23.127 18.873,21.877 19.373,21.377 27.248,21.377 34.748,13.877 94.848,13.877 97.123,11.602 81.623,11.602 80.245,12.98 79.098,12.98 76.92,12.98 77.157,12.98 73.771,9.915 72.962,9.113 72.05,8.209 71.873,8.017 71.748,7.9 71.528,7.692 71.325,7.476 69.925,5.95 69.892,5.953 69.873,5.952 69.798,5.952 69.423,5.952 69.023,5.952 68.723,5.952 68.423,5.952 67.798,5.952 66.573,5.952 64.948,5.952 64.148,5.952 63.748,5.952 63.523,5.952 63.348,5.952 62.948,5.952 62.548,5.952 61.723,5.952 60.098,5.952 56.848,5.952 56.048,5.952 55.223,5.952 53.573,5.952 52.773,5.952 51.948,5.952 51.148,5.952 50.323,5.952 49.523,5.952 48.698,5.952 47.048,5.952 43.798,5.952 41.823,5.952 40.823,5.952 39.823,5.952 39.248,5.952 38.648,5.952 37.498,5.952 37.198,5.952 36.923,5.952 36.348,5.952 35.173,5.952 30.498,5.952 28.498,5.952 26.411,5.952 23.998,5.952 22.423,5.952 22.073,5.952 21.773,5.951 20.748,5.952 19.398,5.952 18.05,5.95 17.724,5.95 17.399,5.95 16.975,5.95 16.65,5.95 16.438,5.95 16.224,5.95 16.181,5.95 16.138,5.95 16.094,5.95 16.071,5.95 16.049,5.95 16.005,5.95 15.983,5.95 15.96,5.95 15.917,5.95 15.875,5.95 15.398,5.475 15.398,5.127 15.398,4.477 15.873,4.002 17.623,4.002 71.873,4.002 78.373,10.877 79.098,10.877 80.348,9.627 99.373,9.627 99.373,5.627 99.723,5.277 101.248,5.277 101.598,5.627 101.598,9.502 108.075,9.502 114.55,9.5 114.548,8.727 117.998,8.727 117.998,-0.023 -0.002,-0.023
GND on Top Layer "Top Layer-No Net" (solid, pour order 8): 0,30 118,30 118,21.25 114.55,21.25 114.55,16.75 109.625,16.75 109.625,22.5 105.8,22.5 105.8,22.25 65.975,22.25 65.975,22.75 61.75,22.75 61.75,18.75 65.5,18.75 65.5,17.8 69.375,17.8 69.375,19.875 74.5,19.875 74.5,20.3 75.725,20.3 75.725,19.875 77.625,19.875 77.625,18.2 77.4,18.2 77.4,15.3 77.7,15.3 77.7,15.1 77.3,15.1 77.3,11 79.85,11 79.85,14.625 79.75,14.625 79.75,19.875 84,19.875 84,14.475 86.25,14.475 86.25,19.875 88.9,19.875 88.9,14.5 91,14.5 91,19.875 100.875,19.875 100.875,15.05 100.875,15.125 100.7,15.125 100.5,15.125 100.5,13.5 98.5,11.5 96.9,11.5 96.9,11.9 93.4,11.9 93.4,9.6 98.7,9.6 99.7,10 100.7,10 100.7,9.1 100,9.1 100,8 97.6,8 97,7.4 93.4,7.4 93.4,4.5 96.5,4.5 97.75,3.75 99.125,3.75 100.5,4.5 103.375,4.5 103.25,4.5 103.25,8.15 103.25,14.75 103.125,14.75 103.125,19.875 105.8,19.875 105.8,18.125 107.25,18.125 107.25,15.125 107.625,14.75 107.875,14.5 108.625,13.75 108.625,13.25 114.55,13.25 114.55,8.75 118,8.75 118,0 0,0 0,8.75 3.45,8.75 3.45,13.375 9.375,13.375 9.375,12.275 10.825,12.275 10.825,10.075 13,10.125 13,12.25 14.625,12.25 14.625,3.5 17.5,3.5 17.5,4.6 24,4.6 24,6.9 22.375,6.9 22.375,8.2 25.2,8.2 25.2,6.2 29.125,6.2 29.125,8.25 28.875,8.25 28.875,8.625 29.35,8.625 29.35,7.5 33.5,7.5 33.5,11.125 29.375,11.125 29.375,10.2 22.15,10.2 22.15,10.575 20.873,10.567 16.6,10.55 16.6,16.025 14.875,16.025 14.875,14.25 12.75,14.25 12.75,16.275 11.525,16.275 11.525,21.5 20.85,21.5 20.85,23.375 5.75,23.375 5.75,21.5 9.275,21.5 9.275,16.625 3.45,16.625 3.45,21.25 0,21.25

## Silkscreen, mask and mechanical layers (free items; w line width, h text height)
Top Overlay:
  text "OUT" at 109.5,12.375 h1
  text "CHIME FLA Rev E" at 66.725,8.975 h1.2
  text "chm-0002-012" at 69.25,6.975 h1.2
  text "FT1" at 97.125,2.725 h1.27
Bottom Overlay:
  text "GND" at 104.975,9.025 h1.52
  text "CHIME FLA Rev E" at 84.6,8.975 h1.2
  text "chm-0002-012" at 83.3,6.925 h1.2
Top Solder:
  circle w1.2: c111,5.8 r2.3
  rectangle: 2.3,27.575 115.9,30
  rectangle: 2.275,27.575 8.55,27.6
  rectangle: 2.3,29.925 8.4,30
  rectangle: 2.275,0 115.75,2.425
  rectangle: 115.75,0 118,8.75
  rectangle: 0,21.3 2.3,30
  rectangle: 115.7,21.3 118,30
  lines w0.127: 102.2,5.4 102.5,5.7
  lines w0.4: 106.252,9.415 cw(c107,9.7) 106.254,9.41
  lines w1.3: -5.75,-30.45 108.75,-30.45 ; 9,1.77 109,1.77 ; 9,28.25 109,28.25
Bottom Solder:
  circle w1.2: c111,5.8 r2.3
  lines w0.4: 106.774,8.933 cw(c107,9.7) 106.878,8.909
Mechanical 1:
  lines w0.127: 0,0 118,0 118,8.75 114.55,8.75 114.55,21.25 118,21.25 118,30 0,30 0,21.25 3.45,21.25 3.45,8.75 0,8.75 0,0
Mechanical 15:
  lines w0.125: 1.635,1.77 8.2,1.77 ; 1.635,21.4 1.635,28 ; 1.635,28.23 8.4,28.23 ; 1.65,2 1.65,8.6 ; 9.6,1.77 18.4,1.77 ; 9.6,28.23 18.4,28.23 ; 19.6,1.77 28.4,1.77 ; 19.6,28.23 28.4,28.23 ; 29.6,1.77 38.4,1.77 ; 29.6,28.23 38.4,28.23 ; 39.6,1.77 48.4,1.77 ; 39.6,28.23 48.4,28.23 ; 49.6,1.77 58.4,1.77 ; 49.6,28.23 58.4,28.23 ; 59.6,1.77 68.4,1.77 ; 59.6,28.23 68.4,28.23 ; 69.6,1.77 78.4,1.77 ; 69.6,28.23 78.4,28.23 ; 79.6,1.77 88.4,1.77 ; 79.6,28.23 88.4,28.23 ; 89.6,1.77 98.4,1.77 ; 89.6,28.23 98.4,28.23 ; 99.6,1.77 108.4,1.77 ; 99.6,28.23 108.4,28.23 ; 109.6,1.77 116.365,1.77 ; 109.7,28.23 116.366,28.23 ; 116.365,2 116.365,8.6 ; 116.365,21.4 116.365,28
